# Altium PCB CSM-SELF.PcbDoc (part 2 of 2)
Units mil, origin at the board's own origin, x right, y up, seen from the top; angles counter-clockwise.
Board outline 6400 x 4000 mil, 2 copper layers (Top Layer, Bottom Layer), stack 62 mil thick; 115 components, 107 nets, 450 pads, 129 vias.
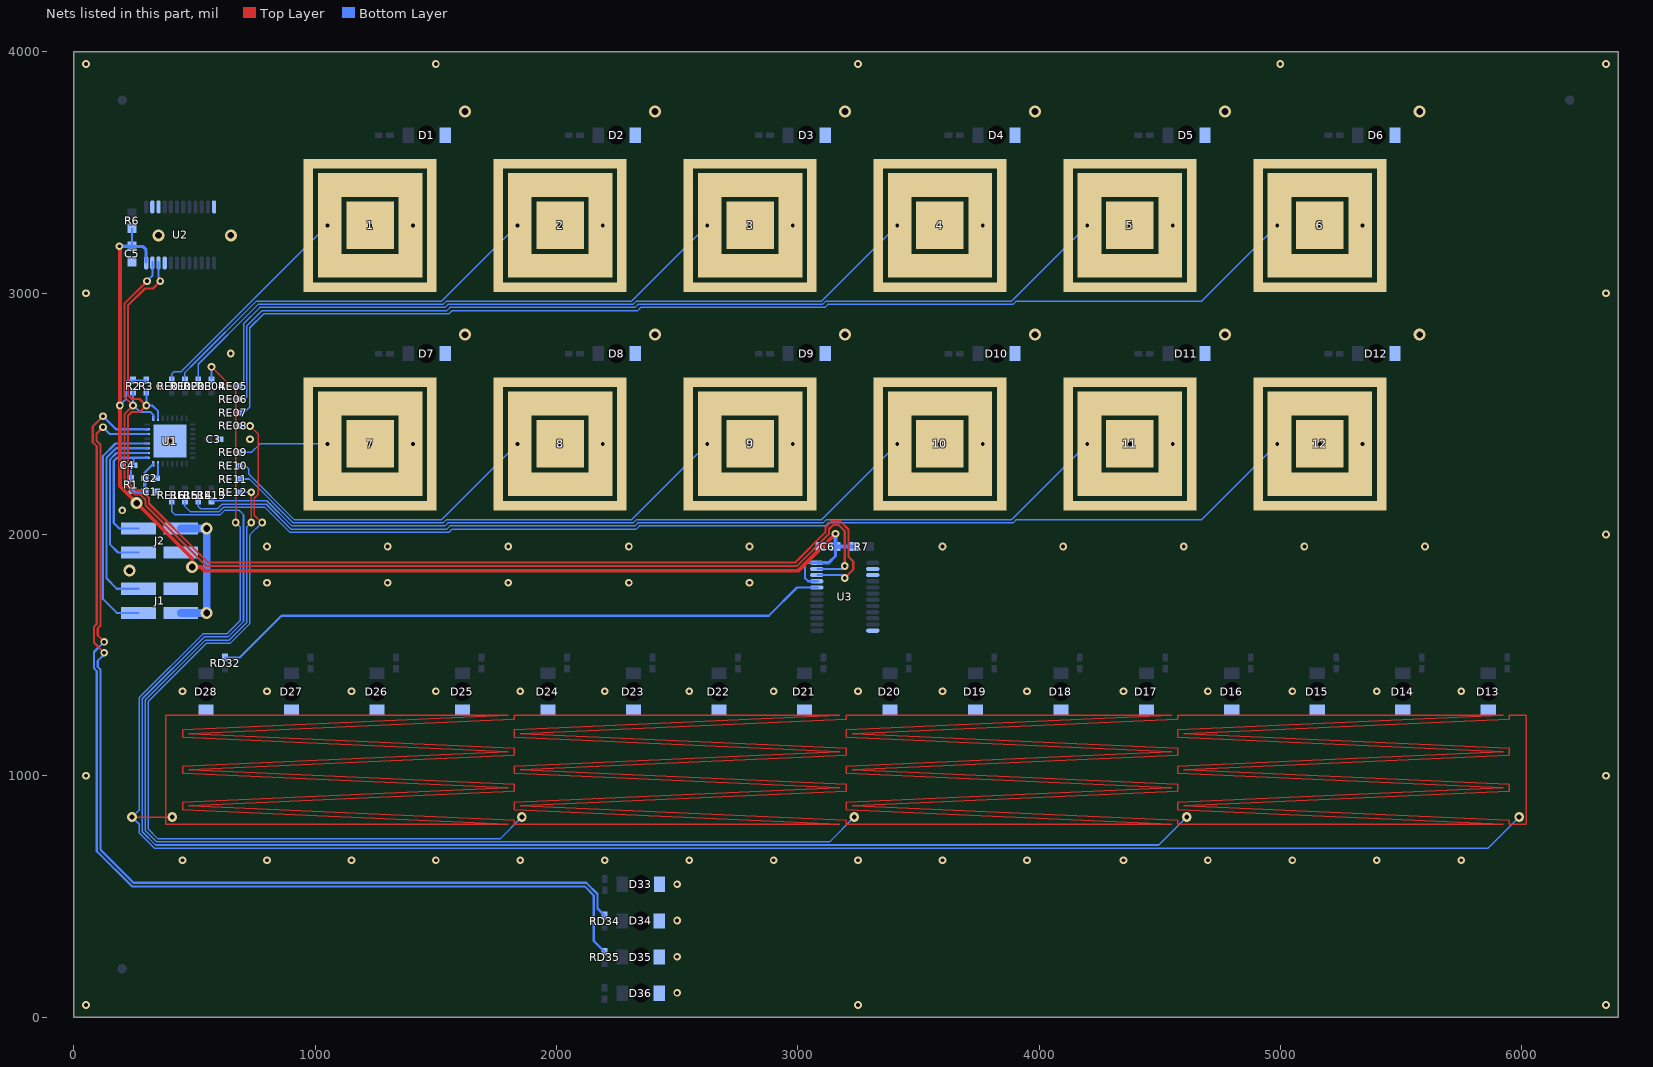
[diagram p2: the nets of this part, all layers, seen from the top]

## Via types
v1: diameter 32, hole 16, Top Layer to Bottom Layer, tented both sides, 103 vias
v2: diameter 50, hole 28, Top Layer to Bottom Layer, tented both sides, 19 vias
v3: diameter 40, hole 20, Top Layer to Bottom Layer, tented both sides, 6 vias
v4: diameter 36, hole 16, Top Layer to Bottom Layer, 1 vias

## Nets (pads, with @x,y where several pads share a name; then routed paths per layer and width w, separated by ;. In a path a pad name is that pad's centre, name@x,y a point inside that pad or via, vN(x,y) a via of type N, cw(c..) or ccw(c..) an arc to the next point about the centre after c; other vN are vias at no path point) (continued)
NetRD32_1: RD32.1 U3.20 | length 2577
  Bottom Layer w9.84: RD32.1@626.06,1490.16 686.77,1490.16 860,1663.39 2880,1663.39 2997.13,1780.51 U3.20@3082.76,1780.51
NOISE: RD35.1 U1.6 | length 4396.7
  Top Layer w9: v1(120,2445) 93.2,2418.2 93.2,2388.9 109.7,2372.4 109.7,1622.6 98.2,1611.1 98.2,1581.8 v1(125,1555)
  Bottom Layer w9: v1(120,2445) 148.49,2416.51 U1.6@303.41,2416.51 ; v1(125,1555) 82.9,1512.9 82.9,1445.16 94.4,1433.66 94.4,687.33 240.2,541.53 2116.84,541.53 2154.7,503.66 2154.7,315.14 RD35.1@2199.21,270.63
RESET: C4.1 J2.2 R1.1 U1.1 | length 601.8
  Bottom Layer w9: R1.1@236.83,2230.29 C4.1@236.83,2289.43 ; C4.1@246.52,2286.98 246.52,2316.57 ; J2.2@267.5,2025 187.59,2025 165,2047.6 165,2305 178.09,2318.09 U1.1@303.41,2318.09
RET: 1.GND 2.GND 3.GND 4.GND 5.GND 6.GND 7.GND 8.GND 9.GND 10.GND 11.GND 12.GND C1.2 C2.2 C3.2 C4.2 C5.2 C6.2 D1.2 D2.2 D3.2 D4.2 D5.2 D6.2 D7.2 D8.2 D9.2 D10.2 D11.2 D12.2 D13.2 D14.2 D15.2 D16.2 D17.2 D18.2 D19.2 D20.2 D21.2 D22.2 D23.2 D24.2 D25.2 D26.2 D27.2 D28.2 D33.2 D34.2 D35.2 D36.2 J1.3 J2.1 U1.31 U1.33 U2.2 U2.3 U2.12 U2.21 U3.2 U3.3 U3.12 | length 616.2
  Bottom Layer w9: C2.2@348.68,2241.28 U1.31@348.68,2292.5
  Bottom Layer w32: J1.3@442.5,1675.01 v2(550,1675) v2(550,2025) J2.1@442.5,2025
  other v1: 50,50 3250,50 6350,50 2500,100 2500,250 2500,400 2500,550 450,650 800,650 1150,650 1500,650 1850,650 2200,650 2550,650 2900,650 3250,650 3600,650 3950,650 4350,650 4700,650 5050,650 5400,650 5750,650 50,1000 6350,1000 450,1350 800,1350 1150,1350 1500,1350 1850,1350 2200,1350 2550,1350 2900,1350 3250,1350 3600,1350 3950,1350 4350,1350 4700,1350 5050,1350 5400,1350 5750,1350 800,1800 1300,1800 1800,1800 2300,1800 2800,1800 800,1950 1300,1950 1800,1950 2300,1950 2800,1950 3600,1950 4100,1950 4600,1950 5100,1950 5600,1950 6350,2000 200,2100 730,2395 355,2615 650,2750 50,3000 6350,3000 50,3950 1500,3950 3250,3950 5000,3950 6350,3950
  other v2: 230,1850 1621.1,2828.35 2408.5,2828.35 3195.91,2828.35 3983.31,2828.35 4770.71,2828.35 5577.8,2828.35 350,3240 650,3240 1621.1,3753.54 2408.5,3753.54 3195.91,3753.54 3983.31,3753.54 4770.71,3753.54 5577.8,3753.54
  other v4: 397.9,2386.98
RUN: RD34.1 U1.7 | length 4303.6
  Top Layer w9: v1(120,2490) 77.9,2447.9 77.9,2382.56 94.4,2366.06 94.4,1628.94 82.9,1617.44 82.9,1552.1 v1(125,1510)
  Bottom Layer w9: v1@120,2488.66 v1(120,2490) 173.8,2436.2 U1.7@303.41,2436.2 ; v1(125,1510) 125,1502.9 98.2,1476.1 98.2,1451.5 109.7,1440 109.7,693.66 246.54,556.83 2123.17,556.83 2170,510 2170,449.84 RD34.1@2199.21,420.63
RX0: 1.RX RE01.2 | length 926.8
  Bottom Layer w6.3: RE01.2@405,2638.62 405,2665 415,2675 444.13,2675 489.8,2720.67 1.RX@1050.24,3281.1
RX1: 2.RX RE02.2 | length 1662.8
  Bottom Layer w6.3: RE02.2@460,2638.62 460,2671.18 502.4,2713.58 754.96,2966.14 1522.68,2966.14 2.RX@1837.64,3281.1
RX2: 3.RX RE03.2 | length 2415.5
  Bottom Layer w6.3: RE03.2@515,2638.62 515,2705.71 762.83,2953.54 1529.76,2953.54 1542.36,2966.14 2310.08,2966.14 3.RX@2625.04,3281.1
RX3: RE04.2 | length 28529.6
  Top Layer w6: 380,800 1800,800 450,860 450,890 1800,950 450,1010 450,1040 1800,1100 450,1160 450,1190 1800,1250 380,1250 380,828.74 380,800 ; 4600,875 5950,935 5950,965 4600,1025 5950,1085 5950,1115 4600,1175 5950,1235 5950,1250 6020,1250 6020,800 5950,800 5950,815 4600,875
  Top Layer w6.3: v3(240.71,828.74) 380,828.74 v3(407.56,828.74) ; v1(570,2695) 670,2595 v1(670,2050)
  Bottom Layer w6.3: RE04.2@570,2645 v1(570,2695) ; v1(670,2050) 690,2030 690,1645 632.8,1587.8 534.34,1587.8 270.55,1324 270.55,858.58 v3(240.71,828.74) 270.55,798.9 270.55,762.69 332.85,700.39 5861.89,700.39 v3(5990.24,828.74)
RX4: 4.RX RE05.2 | length 3144.6
  Bottom Layer w6.3: RE05.2@683.62,2615 703.78,2635.16 703.78,2874.02 770.71,2940.94 1537.64,2940.94 1550.24,2953.54 2317.17,2953.54 2329.76,2966.14 3097.48,2966.14 4.RX@3412.44,3281.1
RX5: 5.RX RE06.2 | length 3986.7
  Bottom Layer w6.3: RE06.2@683.62,2560 705,2560 716.38,2571.38 716.38,2864.57 778.58,2926.77 1543.94,2926.77 1558.11,2940.94 2325.04,2940.94 2337.64,2953.54 3102.7,2953.54 3115.3,2966.14 3884.88,2966.14 5.RX@4199.84,3281.1
RX6: 6.RX RE07.2 | length 4817.1
  Bottom Layer w6.3: RE07.2@683.62,2505 705,2505 728.98,2528.98 728.98,2856.69 786.46,2914.17 1553.39,2914.17 1565.98,2926.77 2335.28,2926.77 2349.45,2940.94 3112.44,2940.94 3125.04,2953.54 3891.97,2953.54 3904.57,2966.14 4672.28,2966.14 6.RX@4987.24,3281.1
RX7: RE08.2 | length 22704.9
  Top Layer w6: 475,875 1825,935 1825,965 475,1025 1825,1085 1825,1115 475,1175 1825,1235 1825,1250 3175,1250 1825,1190 1825,1160 3175,1100 1825,1040 1825,1010 3175,950 1825,890 1825,860 3175,800 1825,800 1825,815 475,875
  Top Layer w6.3: v1(730,2450) 763.91,2416.09 763.91,2166.09 747.6,2149.78 747.6,2080 777.6,2050 v1(780,2050)
  Bottom Layer w6.3: RE08.2@683.62,2450 v1(730,2450) ; v1(780,2050) 727.8,1997.8 727.8,1629.34 648.45,1550 550,1550 308.35,1308.35 308.35,778.35 348.5,738.19 1765.83,738.19 v3(1856.38,828.74)
RX8: 7.RX RE09.2 | length 381.4
  Bottom Layer w6.3: RE09.2@683.62,2340 735,2340 770.59,2375.59 7.RX@1050.24,2375.59
RX9: 8.RX RE10.2 | length 1389.1
  Bottom Layer w6.3: RE10.2@683.62,2285 710,2285 725,2270 725,2250 914.37,2060.63 1522.68,2060.63 8.RX@1837.64,2375.59
RX10: 9.RX RE11.2 | length 2152.5
  Bottom Layer w6.3: RE11.2@683.62,2230 727.18,2230 909.15,2048.03 1529.76,2048.03 1542.36,2060.63 2310.08,2060.63 9.RX@2625.04,2375.59
RX11: RE12.2 | length 23794.9
  Top Layer w6: 1850,875 3200,935 3200,965 1850,1025 3200,1085 3200,1115 1850,1175 3200,1235 3200,1250 4550,1250 3200,1190 3200,1160 4550,1100 3200,1040 3200,1010 4550,950 3200,890 3200,860 4550,800 3200,800 3200,815 1850,875
  Top Layer w6.3: v1(735,2050) v1(735,2175)
  Bottom Layer w6.3: RE12.2@683.62,2175 v1(735,2175) v1@740,2175 ; v1(735,2050) 715.2,2030.2 715.2,1634.56 643.23,1562.6 544.78,1562.6 295.75,1313.56 295.75,773.13 343.29,725.59 3131.18,725.59 v3(3234.33,828.74)
RX12: 10.RX RE13.2 | length 3026.7
  Bottom Layer w6.3: RE13.2@570,2140 799.37,2140 903.93,2035.43 1537.64,2035.43 1550.24,2048.03 2317.17,2048.03 2329.76,2060.63 3097.48,2060.63 10.RX@3412.44,2375.59
RX13: 11.RX RE14.2 | length 3910.1
  Bottom Layer w6.3: RE14.2@515,2140 515,2116.38 525,2106.38 595,2106.38 613.62,2125 796.55,2125 900.29,2021.26 1543.94,2021.26 1558.11,2035.43 2325.04,2035.43 2337.64,2048.03 3104.57,2048.03 3117.17,2060.63 3884.88,2060.63 11.RX@4199.84,2375.59
RX14: 12.RX RE15.2 | length 4762.9
  Bottom Layer w6.3: RE15.2@460,2140 460,2116.38 482.6,2093.78 600.22,2093.78 618.84,2112.4 791.33,2112.4 895.07,2008.66 1553.39,2008.66 1565.98,2021.26 2329.76,2021.26 2343.94,2035.43 3112.44,2035.43 3125.04,2048.03 3891.97,2048.03 3904.57,2060.63 4672.28,2060.63 12.RX@4987.24,2375.59
RX15: RE16.2 | length 25405
  Top Layer w6: 3225,875 4575,815 4575,800 5925,800 4575,860 4575,890 5925,950 4575,1010 4575,1040 5925,1100 4575,1160 4575,1190 5925,1250 4575,1250 4575,1235 3225,1175 4575,1115 4575,1085 3225,1025 4575,965 4575,935 3225,875
  Bottom Layer w6.3: RE16.2@405,2140 405,2095 418.82,2081.18 605.44,2081.18 624.06,2099.8 685.2,2099.8 702.6,2082.4 702.6,1639.78 638.01,1575.2 539.56,1575.2 283.15,1318.78 283.15,767.91 338.07,712.99 4496.54,712.99 v3(4612.28,828.74)
RXD: J1.4 U1.4 | length 969.5
  Bottom Layer w9: J1.4@267.5,1675.01 177.59,1675.01 119.1,1733.49 119.1,2324.01 172.23,2377.14 U1.4@303.41,2377.14
SCL: R3.2 U1.10 U2.22 U3.22 | length 4813
  Top Layer w9: v1(357.48,3050) 327.48,3020 294.12,3020 224.1,2949.98 224.1,2577.54 239.84,2561.8 271.8,2561.8 298.6,2535 v1(300,2535) 272.5,2507.5 239.14,2507.5 224.1,2492.46 224.1,2215.45 258.45,2181.1 281.17,2181.1 311.1,2151.17 311.1,2128.45 521.45,1918.1 521.9,1918.1 555.9,1884.1 2989.26,1884.1 3114.4,2009.23 3114.4,2029.3 3140,2054.91 3176.34,2054.91 3210.3,2020.94 3210.3,1907.48 3230,1887.78 3230,1854.61 v1(3195,1819.61)
  Bottom Layer w9: R3.2@300,2591.38 v1(300,2535) 325,2535 348.68,2511.32 U1.10@348.68,2481.47 ; U2.22@350.43,3129.53 350.43,3057.05 v1(357.48,3050) ; U3.22@3082.76,1831.69 3182.91,1831.69 v1(3195,1819.61)
SDA: R2.2 U1.9 U2.23 U3.23 | length 4665.1
  Top Layer w9: v1(302.48,3050) 208.8,2956.32 208.8,2571.2 v1(245,2535) 208.8,2498.8 208.8,2209.11 252.11,2165.8 274.83,2165.8 295.8,2144.83 295.8,2122.11 549.11,1868.8 2995.6,1868.8 3129.7,2002.9 3129.7,2022.72 3146.59,2039.61 3170,2039.61 3195,2014.61 v1(3195,1869.61)
  Bottom Layer w7.87: R2.2@245,2591.38 v1(245,2535) 271.76,2508.24 316.76,2508.24 329,2496 U1.9@329,2481.47
  Bottom Layer w9: v1(302.48,3050) 324.84,3072.36 U2.23@324.84,3129.53 ; U3.23@3082.76,1857.28 3182.68,1857.28 v1(3195,1869.61)
TEST: J2.4 U1.2 | length 649.5
  Bottom Layer w9: J2.4@267.5,1925 182.59,1925 149.7,1957.9 149.7,2311.34 176.14,2337.77 U1.2@303.41,2337.77
TXD: J1.2 U1.3 | length 836
  Bottom Layer w9: J1.2@267.5,1775.01 177.59,1775.01 134.4,1818.19 134.4,2317.67 174.18,2357.46 U1.3@303.41,2357.46
VCC: C1.1 C2.1 C5.1 C6.1 J1.1 J2.3 R1.2 R2.1 R3.1 R6.1 R7.1 U1.32 U2.24 U3.21 U3.24 | length 5229.1
  Top Layer w16: v1@190,3192.48 v1(190,2535) 190,2200 v2(260,2130) 490,1900 v2(490,1865) 526.33,1865 541.33,1850 3003.39,1850 v1(3156.5,2003.11)
  Bottom Layer w7.87: C5.1@241.18,3194.49 R6.1@241.18,3269.29
  Bottom Layer w9: v1(190,2535) 215,2560 215,2630 223.62,2638.62 R2.1@245,2638.62 R3.1@300,2638.62 ; C2.1@293.21,2233.05 293.21,2256.71 U1.32@329,2292.5 ; U3.21@3082.76,1806.1 3042.95,1806.1 3030,1819.06 3030,1874.61 3038.27,1882.87 U3.24@3082.76,1882.87
  Bottom Layer w12.6: C5.1@241.18,3194.49 284.49,3194.49 299.25,3179.72 U2.24@299.25,3129.53
  Bottom Layer w13: U3.24@3082.76,1882.87 3128.27,1882.87 3156.5,1911.1 C6.1@3156.5,1949.61
  Bottom Layer w16: v1(187.99,3194.49) C5.1@241.18,3194.49 ; R1.2@241.83,2178.05 C1.1@293.21,2178.05 C2.1@293.21,2233.05 ; v1(3156.5,2003.11) C6.1@3156.5,1949.61 R7.1@3233.5,1949.61
pads on no net: D1. D2. D3. D4. D5. D6. D7. D8. D9. D10. D11. D12. D13. D14. D15. D16. D17. D18. D19. D20. D21. D22. D23. D24. D25. D26. D27. D28. D33. D34. D35. D36. FID1.1 FID2.1 FID3.1 U1.11 U1.29 U1.30 U2.17 U2.18 U2.19 U2.20

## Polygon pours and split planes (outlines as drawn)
RET on Top Layer "Top Layer Return Plane" (solid, remove dead copper, pour order 14): 6380,3980 20,3980 20,20 6380,20 6380,3980
RX15 on Top Layer "Top Layer-No Net 2" (solid, remove dead copper, pour order 18): 3225,875 4575,935 4575,965 3225,1025 4575,1085 4575,1115 3225,1175 4575,1235 4575,1250 5925,1250 4575,1190 4575,1160 5925,1100 4575,1040 4575,1010 5925,950 4575,890 4575,860 5925,800 4575,800 4575,815
RX11 on Top Layer "Top Layer-No Net 1" (solid, remove dead copper, pour order 17): 1850,875 3200,935 3200,965 1850,1025 3200,1085 3200,1115 1850,1175 3200,1235 3200,1250 4550,1250 3200,1190 3200,1160 4550,1100 3200,1040 3200,1010 4550,950 3200,890 3200,860 4550,800 3200,800 3200,815
RX7 on Top Layer "Top Layer-No Net" (solid, remove dead copper, pour order 16): 475,1025 1825,965 1825,935 475,875 1825,815 1825,800 3175,800 1825,860 1825,890 3175,950 1825,1010 1825,1040 3175,1100 1825,1160 1825,1190 3175,1250 1825,1250 1825,1235 475,1175 1825,1115 1825,1085
RX3 on Top Layer "Top Layer-CAPT_A.2" (solid, remove dead copper, pour order 15): 380,800 380,1250 1800,1250 450,1190 450,1160 1800,1100 450,1040 450,1010 1800,950 450,890 450,860 1800,800
RX3 on Top Layer "Top Layer-CAPT_D.2" (solid, remove dead copper, pour order 12): 4600,1025 5950,965 5950,935 4600,875 5950,815 5950,800 6020,800 6020,1250 5950,1250 5950,1235 4600,1175 5950,1115 5950,1085
RET on Bottom Layer "Bottom Layer Return Plane" (hatched 45Degree grid 32 track 8, remove dead copper, pour order 13): 6380,3980 20,3980 20,20 6380,20 6380,3980
VCC on Bottom Layer "MCU VCC Plane" (solid, remove dead copper, pour order 11): 308.9,2244.98 270.65,2244.98 258.65,2232.98 258.65,2208.98 248.65,2198.98 225.02,2198.98 225.02,2120.61 248.65,2096.98 279.9,2096.98 291.9,2108.98 291.9,2127.98 291.9,2146.98 309.9,2164.98 308.9,2165.98 308.9,2244.98
VCC on Bottom Layer "VCC Plane" (solid, remove dead copper, pour order 10): 515,1750 515,1950 370,1950 370,1750 515,1750

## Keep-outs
Keep-Out Layer:
  text ".Layer_Name" at 578,-857.99 h60

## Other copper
Top Layer:
  text ".Layer_Name" at 578,-857.99 h60
Bottom Layer:
  text ".Layer_Name" at 578,-857.99 h60

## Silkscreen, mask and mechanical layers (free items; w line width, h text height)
Top Overlay:
  lines w20: 453,778 5949,777.56 ccw(c5949,877.56) 6049,877.56 6049.29,1170 ccw(c5949.29,1170) 5949.29,1270 460.32,1270 ccw(c460.32,1170) 360.32,1170 360.32,878 ccw(c460.32,878) 460.32,778
  lines w25: 50,350 2052.46,350.62 ; 2050,350 ccw(c2050,450) 2150,450 2150,550 cw(c2250,550) 2250,650 4200,650 cw(c4200,550) 4300,550 4300,450 ccw(c4400,450) 4400,350 6350,350
  text "Detection" at 2550,510 h125
  text "CSM-SELF" at 3326.1,420 h150
  text "Run" at 2550,360 h125
  text "TIDM-CAPTOUCHEMCREF" at 3110,240 h100
  text "TM" at 5830,220 h60
  text "Noise" at 2550,210 h125
  text "Capacitive Sensing Module" at 3100,140 h100
  text "MSP CapTIvate  MCUs" at 4890,130 h150
  text "Fault" at 2550,60 h125
  text ".Layer_Name" at 578,-857.99 h60
Bottom Overlay:
  text "RST" at 165,2000 h75
  text "RET" at 675,2000 h75
  text "TST" at 165,1900 h75
  text "VCC" at 685,1900 h75
  text "TXD" at 165,1750 h75
  text "VCC" at 685,1750 h75
  text "RXD" at 165,1650 h75
  text "RET" at 675,1650 h75
  text "TM" at 5095,745 h70
  text "MSP CapTIvate  MCUs" at 6200,650 h175
  text "Capacitive Touch MCU TI Design" at 6200,530 h125
  text "www.ti.com/captivate" at 6200,420 h125
  text ".PRJ_Number" at 6200,310 h125
  text ".PCB_Rev" at 5740,200 h125
  text "Revision" at 6200,200 h125
  text ".Layer_Name" at 578,-857.99 h60
Top Paste:
  text ".Layer_Name" at 578,-857.99 h60
Bottom Paste:
  text ".Layer_Name" at 578,-857.99 h60
Top Solder:
  text ".Layer_Name" at 578,-857.99 h60
  text ".Layer_Name" at 578,-857.99 h60
Bottom Solder:
  text ".Layer_Name" at 578,-857.99 h60
Drill Guide:
  text ".Layer_Name" at 578,-857.99 h60
M1 Board Outline:
  the board outline again, w20
  text ".Layer_Name" at 578,-857.99 h60
M2 Board Dimensions:
  rectangle: 126,-399.5 501,-274.5
  rectangle: 1,-274.5 126,-149.5
  rectangle: 125,-400 500,-275
  rectangle: 0,-275 125,-150
  lines w7: 0,-275 1000,-275 ; 1,-274.5 1001,-274.5 ; 1,-149.5 1,-399.5 1001,-399.5 1001,-149.5 ; 125,-400 125,-150 ; 126,-399.5 126,-149.5 ; 250,-400 250,-150 ; 251,-399.5 251,-149.5 ; 500,-400 500,-150 ; 501,-399.5 501,-149.5 ; 750,-400 750,-150 ; 751,-399.5 751,-149.5 ; 0,-400 0,-150 1000,-150 1000,-400 0,-400
  text ".Layer_Name" at 578,-857.99 h60
M3 3D STEP Top:
  text ".Layer_Name" at 578,-857.99 h60
M4 3D STEP Bottom:
  text ".Layer_Name" at 578,-857.99 h60
M5 Assembly Top:
  lines w10: -291,-1133 3714,-1133 ; -290.5,-1133 1285,-1133 ; -290.5,-523 6311,-523 6311,-1133 ; 4903,-1139.5 4903,-936.67 ; -291,-929.67 6309,-929.67 ; -291,-929.67 6309,-929.67 ; -291,-929.67 6309,-929.67 ; -291,-929.67 6309,-929.67 ; -291,-726.33 6311,-726.33 ; -291,-726.33 6311,-726.33 ; -291,-726.33 6311,-726.33 ; -291,-726.33 6311,-726.33 ; 3714,-1133 6311,-1133 ; 3714,-1133 6311,-1133 ; 3714,-1133 6311,-1133 ; 3714,-1133 6311,-1133
  text "COMPONENTS MARKED 'DNP' SHOULD NOT BE POPULATED." at 1153.5,-318.5 h60
  text "COMPONENTS MARKED 'DNP' SHOULD NOT BE POPULATED." at 1154.5,-318 h60
  text "ASSEMBLY VARIANT:" at 1153,-434 h60
  text "ASSEMBLY VARIANT:" at 1154,-433.5 h60
  text ".VariantName" at 2189,-434 h60
  text ".VariantName" at 2190,-433.5 h60
  text "PCB VIEWED FROM TOP SIDE" at -227.5,-655.17 h60
  text "BOARD #:" at 2249,-655.17 h60
  text ".PRJ_Number" at 2794.5,-655.17 h60
  text "REV:" at 3639,-655.17 h60
  text ".PCB_Rev" at 3930.5,-655.17 h60
  text "SVN REV:" at 4477,-655.17 h60
  text ".VersionControl_RevNumber" at 4983,-655.17 h60
  text "TID #:" at 2249,-858.5 h60
  text ".TID" at 2794.5,-858.5 h60
  text "PLOT NAME =" at -227.5,-1063.84 h60
  text ".plot_File_Name" at 578,-1063.84 h60
  text "GENERATED    :" at 2251,-1063.84 h60
  text ".Print_Date" at 3120.5,-1063.84 h60
  text ".Print_Time" at 3849.5,-1063.84 h60
  text "TEXAS INSTRUMENTS" at 5114,-1063.84 h60
M6 Assembly Bottom:
  lines w10: -291.5,-1133.5 2305.5,-1133.5 ; -291.5,-523.5 6310,-523.5 6310,-1133.5 ; 1116.5,-1140 1116.5,-937.17 ; 6310.5,-523.5 6310.5,-1133.5 ; -291.5,-726.83 6310.5,-726.83 ; -291.5,-726.83 6310.5,-726.83 ; -291.5,-726.83 6310.5,-726.83 ; -291.5,-726.83 6310.5,-726.83 ; -289.5,-930.17 6310.5,-930.17 ; -289.5,-930.17 6310.5,-930.17 ; -289.5,-930.17 6310.5,-930.17 ; -289.5,-930.17 6310.5,-930.17 ; 2305.5,-1133.5 6310.5,-1133.5 ; 2305.5,-1133.5 6310.5,-1133.5 ; 2305.5,-1133.5 6310.5,-1133.5 ; 2305.5,-1133.5 6310.5,-1133.5 ; 4734.5,-1133.5 6310,-1133.5 ; 4734.5,-1133.5 6310,-1133.5 ; 4734.5,-1133.5 6310,-1133.5 ; 4734.5,-1133.5 6310,-1133.5
  text "COMPONENTS MARKED 'DNP' SHOULD NOT BE POPULATED." at 6103,-317.5 h60
  text ".VariantName" at 5059,-433.5 h60
  text "ASSEMBLY VARIANT:" at 6098,-433.5 h60
  text ".VersionControl_RevNumber" at 1036.5,-655.67 h60
  text "SVN REV:" at 1542.5,-655.67 h60
  text ".PCB_Rev" at 2089,-655.67 h60
  text "REV:" at 2380.5,-655.67 h60
  text ".PRJ_Number" at 3225,-655.67 h60
  text "BOARD #:" at 3770.5,-655.67 h60
  text "PCB VIEWED FROM BOTTOM SIDE" at 6247,-655.67 h60
  text ".TID" at 3225,-859 h60
  text "TID #:" at 3770.5,-859 h60
  text "TEXAS INSTRUMENTS" at 905.5,-1064.34 h60
  text ".Print_Time" at 2170,-1064.34 h60
  text ".Print_Date" at 2899,-1064.34 h60
  text "GENERATED    :" at 3768.5,-1064.34 h60
  text ".plot_File_Name" at 5441.5,-1064.34 h60
  text "PLOT NAME =" at 6247,-1064.34 h60
M9 Title Sheet:
  drawing of 58 lines, arcs and shapes, not listed
  text "1" at 739.84,8036.5 h70
  text "2" at 3235.5,8036.5 h70
  text "3" at 5724.84,8036.5 h70
  text "4" at 8231.51,8036.5 h70
  text "5" at 10730.5,8036.5 h70
  text "6" at 13235.5,8036.5 h70
  text "A" at -416.5,6893.5 h70
  text "A" at 14383.5,6893.5 h70
  text "B" at -416.5,4513.5 h70
  text "B" at 14383.5,4513.5 h70
  text "C" at -416.5,2138.5 h70
  text "C" at 14383.5,2138.5 h70
  text "PROJECT TITLE:" at 11343.5,277.5 h45
  text ".PRJ_Title" at 11393.5,144.17 h70
  text "DESIGNED FOR:" at 11343.5,-23.5 h45
  text ".PRJ_Customer" at 11393.5,-163.5 h70
  text "D" at -416.5,-231.5 h70
  text "D" at 14383.5,-231.5 h70
  text "FILE NAME:" at 11343.5,-323.5 h45
  text ".PCB_File_Name_No_Path" at 11393.5,-443.5 h70
  text "Texas Instruments (TI) and/or its licensors do not warrant the accuracy or completeness of this specification" at 6374,-605.34 h45
  text "ENGINEER:" at 11343.5,-613.5 h45
  text "LAYOUT BY:" at 12848.5,-613.5 h45
  text "or any information contained therein. TI and/or its licensors do not warrant that this design will meet" at 6329.01,-718 h45
  text ".PRJ_Engineer" at 11393.5,-768.49 h70
  text ".PCB_Layout" at 12899,-768.49 h70
  text "the specifications, will be suitable for your application or fit for any particular purpose, or will operate in" at 6329.01,-830.67 h45
  text ".Layer_Name" at 578,-857.99 h60
  text "ALTIUM DESIGNER VERSION:" at 12848.5,-923.5 h45
  text "an implementation. TI and/or its licensors do not warrant that the design is production worthy. You should" at 6329.01,-943.33 h45
  text "completely validate and test your design implementation to confirm the system functionality for your application." at 6374,-1056 h45
  text ".print_Scale" at 11393.5,-1056.83 h70
  text ".Application_BuildNumber" at 12899,-1056.83 h70
  text "1" at 739.84,-1263.5 h70
  text "2" at 3235.5,-1263.5 h70
  text "3" at 5724.84,-1263.5 h70
  text "4" at 8231.51,-1263.5 h70
  text "5" at 10730.5,-1263.5 h70
  text "6" at 13235.5,-1263.5 h70
M10 Fab Notes:
  drawing of 185 lines, arcs and shapes, not listed
  text "DESIGN INFORMATION" at 12381.02,5910 h60
  text "MIN. TRACK WIDTH:" at 11736.46,5730 h60
  text "MIL" at 12987.46,5730 h60
  text "6" at 12824.7,5722 h60
  text "MIN. CLEARANCE:" at 11736.46,5598 h60
  text "6" at 12772.7,5598 h60
  text "MIL" at 12987.46,5598 h60
  text "MIN. VIA PAD SIZE:" at 11736.46,5466 h60
  text "1" at 12802.71,5466 h60
  text "mm" at 12987.46,5466 h60
  text "0.05mm (2MIL)" at 12431.46,5324.29 h60
  text "MINIMUM ANNULAR RING" at 11407.23,5320 h60
  text "EXTERNAL" at 13139.46,5320 h60
  text "PER" at 11607.23,5202 h60
  text "IPC-D-275 CLASS 2 LEVEL C" at 11827.23,5202 h60
  text "MIL, HOLES" at 13315.46,5089.71 h60
  text "+/-" at 12923,5089 h60
  text "+/-" at 13777,5089 h60
  text "REGISTRATION TOLERANCES:" at 11407.23,5084 h60
  text "METAL" at 12607,5084 h60
  text "5" at 13183.2,5084 h60
  text "3" at 14016.2,5084 h60
  text "MIL" at 14132.46,5084 h60
  text "MATERIAL:" at 11332.46,4874.54 h60
  text "FR-4 High Tg" at 12318.9,4734.21 h60
  text "FR-408" at 11753.46,4725.64 h60
  text "X" at 12165.46,4725.64 h60
  text "OTHER" at 13241.46,4725.64 h60
  text "62 MIL (1.6mm) +/-10%" at 12073.56,4562.92 h60
  text "THICKNESS:" at 11407.23,4558.64 h60
  text "X" at 11945.4,4558.64 h60
  text "OTHER" at 13358.46,4558.64 h60
  text "TOLERANCE:" at 11407.23,4400.64 h60
  text "X" at 12246.53,4400.64 h60
  text "ANSI IPC-6012 TYPE 3 CLASS 2" at 12433.48,4400.64 h60
  text "OTHER +/-" at 12433.46,4244.64 h60
  text "BOW & TWIST:" at 11407.23,4087.64 h60
  text "X" at 12246.53,4087.64 h60
  text "ANSI IPC-6012 TYPE 3 CLASS 2" at 12433.48,4087.64 h60
  text "OTHER +/-" at 12433.46,3929.13 h60
  text "DRILLING:" at 11332.46,3790.64 h60
  text "REFERENCE:" at 11407.23,3673.64 h60
  text "X" at 12055.46,3673.64 h60
  text "AS SHOWN" at 12242.46,3673.64 h60
  text "X" at 12956.46,3673.64 h60
  text "NC_DRILL FILES" at 13093.46,3673.64 h60
  text "PTH MIN COPPER THICKNESS:" at 11407.23,3515.64 h60
  text "X" at 12757.46,3515.64 h60
  text "1MIL" at 12894.46,3515.64 h60
  text "OTHER" at 13391.46,3515.64 h60
  text "BOARD FINISH:" at 11332.46,3356.64 h60
  text "SILKSCREEN:" at 11487.68,3238.64 h60
  text "X" at 12436.46,3238.64 h60
  text "TOP" at 12562.46,3238.64 h60
  text "X" at 12946.46,3238.64 h60
  text "BOTTOM" at 13073.46,3238.64 h60
  text "SILKSCREEN COLOR:" at 11487.68,3071.64 h60
  text "X" at 12435.42,3071.64 h60
  text "WHITE" at 12562.46,3071.64 h60
  text "OTHER" at 13073.46,3071.64 h60
  text "SOLDER RESIST COLOR:" at 11487.68,2901.64 h60
  text "X" at 12055.42,2742.44 h60
  text "GREEN" at 12182.46,2742.44 h60
  text "BLUE" at 12773.46,2742.44 h60
  text "OTHER" at 13311.46,2742.44 h60
  text "IMMERSION GOLD (ENIG)" at 12393.46,2553.92 h60
  text "ENEPIG" at 13731,2550.64 h60
  text "SURFACE FINISH:" at 11332.46,2549.64 h60
  text "X" at 12206.51,2549.64 h60
  text "IMM. TIN/SILVER OR EQUIV" at 11662,2392.64 h60
  text "OTHER" at 13093.46,2392.64 h60
  text "ARRAY/PANEL:" at 11332.46,2213.64 h60
  text "CUT AND TRIM PER MECH LAYER 1" at 12393.46,2209.35 h60
  text "N.C. ROUTE" at 12393.46,2057.64 h60
  text "X" at 13072.46,2057.64 h60
  text "V. SCORE" at 13259.46,2057.64 h60
  text "CERTIFICATION:" at 11332.46,1920.64 h60
  text "MATERIALS AND WORKMANSHIP FOR ALL PCBS" at 12057.46,1920.64 h60
  text "TO MEET OR EXCEED THE REQUIREMENTS OF:" at 12057.46,1822.64 h60
  text "X" at 11683.96,1686.13 h60
  text "ANSI IPC-A-600F CLASS ->" at 11822.96,1686.13 h60
  text "X" at 13462.02,1686.13 h60
  text "2" at 13580.96,1686.14 h60
  text "1" at 13265.96,1684.64 h60
  text "3" at 13934.96,1684.64 h60
  text "X" at 11686.02,1526.64 h60
  text "UL 94V-0" at 11822.96,1526.64 h60
  text "X" at 12498.02,1526.64 h60
  text "RoHS" at 12634.96,1526.64 h60
  text "OTHER" at 13279.36,1526.64 h60
  text "PER ORDER" at 13676.42,1526.64 h60
  text "ADDITIONAL REQUIREMENTS:" at 11332.46,1385.64 h60
  text "MICROSECTION:" at 11407.23,1270.64 h60
  text "YES" at 12312.96,1270.64 h60
  text "REQUIRED" at 13174.46,1114.49 h60
  text "BARE BOARD ELEC. TEST:" at 11407.23,1111.64 h60
  text "NONE" at 12712.96,1111.64 h60
  text "X" at 13047.46,1111.64 h60
  text "PER ORDER" at 13766.46,1111.64 h60
  text "MANUFACTURER'S UL:" at 11407.23,954.64 h60
  text "RAIL" at 12572.96,950.35 h60
  text "METAL" at 13064.77,950.35 h60
  text "X" at 13440,950 h60
  text "SILK" at 13576.46,950.35 h60
  text ".Layer_Name" at 578,-857.99 h60
M11 Gerber Information:
  lines w10: -291,-1133 3714,-1133 ; -290.5,-1133 1285,-1133 ; -290.5,-523 6311,-523 6311,-1133 ; 4903,-1139.5 4903,-936.67 ; -291,-929.67 6309,-929.67 ; -291,-929.67 6309,-929.67 ; -291,-929.67 6309,-929.67 ; -291,-929.67 6309,-929.67 ; -291,-726.33 6311,-726.33 ; -291,-726.33 6311,-726.33 ; -291,-726.33 6311,-726.33 ; -291,-726.33 6311,-726.33 ; 3714,-1133 6311,-1133 ; 3714,-1133 6311,-1133 ; 3714,-1133 6311,-1133 ; 3714,-1133 6311,-1133
  text "ALL ARTWORK VIEWED FROM TOP SIDE" at -227.5,-655.17 h60
  text "BOARD #:" at 2249,-655.17 h60
  text ".PRJ_Number" at 2794.5,-655.17 h60
  text "REV:" at 3639,-655.17 h60
  text ".PCB_Rev" at 3930.5,-655.17 h60
  text "SVN REV:" at 4477,-655.17 h60
  text ".VersionControl_RevNumber" at 4983,-655.17 h60
  text "LAYER NAME =" at -227.5,-857.99 h60
  text "TID #:" at 2249,-858.5 h60
  text ".TID" at 2794.5,-858.5 h60
  text "PLOT NAME =" at -227.5,-1063.84 h60
  text ".plot_File_Name" at 578,-1063.84 h60
  text "GENERATED    :" at 2251,-1063.84 h60
  text ".Print_Date" at 3120.5,-1063.84 h60
  text ".Print_Time" at 3849.5,-1063.84 h60
  text "TEXAS INSTRUMENTS" at 5114,-1063.84 h60
M12 Stackup:
  drawing of 191 lines, arcs and shapes, not listed
  text "Layer" at 9790.34,7830 h60
  text "Name" at 10200.26,7830 h60
  text "Material" at 11130,7830 h60
  text "Thickness" at 11989.77,7830 h60
  text "Constant" at 12639.6,7830 h60
  text "Board Layer Stack" at 13209.46,7830 h60
  text "1" at 9790.34,7710 h60
  text "Top Overlay" at 10200.26,7710 h60
  text "2" at 9790.34,7590 h60
  text "Top Solder" at 10200.26,7590 h60
  text "Solder Resist" at 11130,7590 h60
  text "0.40mil" at 11989.77,7590 h60
  text "3.5" at 12639.6,7590 h60
  text "3" at 9790.34,7470 h60
  text "Top Layer" at 10200.26,7470 h60
  text "Copper" at 11130,7470 h60
  text "1.40mil" at 11989.77,7470 h60
  text "4" at 9790.34,7350 h60
  text "Dielectric1" at 10200.26,7350 h60
  text "FR-4" at 11130,7350 h60
  text "59.20mil" at 11989.77,7350 h60
  text "4.8" at 12639.6,7350 h60
  text "5" at 9790.34,7230 h60
  text "Bottom Layer" at 10200.26,7230 h60
  text "Copper" at 11130,7230 h60
  text "1.40mil" at 11989.77,7230 h60
  text "6" at 9790.34,7110 h60
  text "Bottom Solder" at 10200.26,7110 h60
  text "Solder Resist" at 11130,7110 h60
  text "0.40mil" at 11989.77,7110 h60
  text "3.5" at 12639.6,7110 h60
  text "7" at 9790.34,6990 h60
  text "Bottom Overlay" at 10200.26,6990 h60
  text ".Layer_Name" at 578,-857.99 h60
M13 Component Bodies Top:
  text ".Layer_Name" at 578,-857.99 h60
M14 Component Bodies Bottom:
  text ".Layer_Name" at 578,-857.99 h60
M15 Courtyards Top:
  text ".Layer_Name" at 578,-857.99 h60
M16 Courtyards Bottom:
  text ".Layer_Name" at 578,-857.99 h60
Drill Drawing:
  text ".Layer_Name" at 578,-857.99 h60

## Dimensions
1,-399.5 to 1001,-399.5 on M2 Board Dimensions
0,-400 to 1000,-400 on M2 Board Dimensions
0,4000 to 6400,4000 on M2 Board Dimensions
6400,4000 to 6400,0 on M2 Board Dimensions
